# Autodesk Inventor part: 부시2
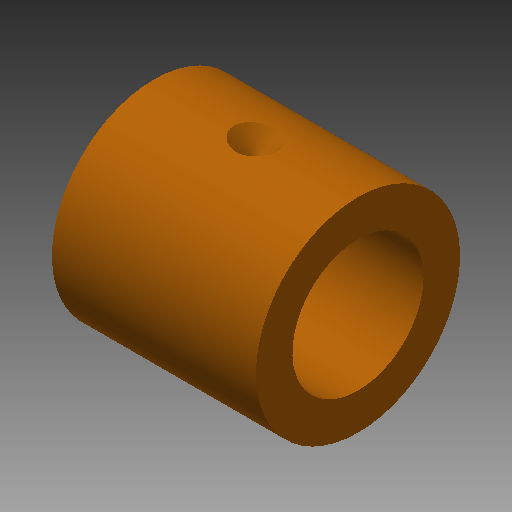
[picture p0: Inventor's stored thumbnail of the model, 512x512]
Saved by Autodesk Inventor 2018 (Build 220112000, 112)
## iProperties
Created: 2020-03
Part Number: 부시2
Material: 스테인리스강
Document SubType Name: Modeling
Designer: mduedu
Density: 8.08 g/cm^3
Appearance: 주황색
Mass: 10.1904 g
Surface Area: 11.9486 cm^2
Volume: 1.26119 cm^3
Author: mduedu
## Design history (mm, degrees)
sketch "스케치2"
  geometry: C1 r 7 at (0, 0); C2 r 4.5 at (0, 0); 1 further point
  constraints: 2 centre point, 2 coincident
  dimensions: "d15" = 14 diameter of C1; "d16" = 9 diameter of C2
extrude "돌출1" new body sketch "스케치2" distance "d17" = 14; taper "d18" = 0 deg
sketch "스케치3"
  geometry: L1 (0, -7)-(-14, -7) reference; L2 (-14, -7)-(-14, -4.5) reference; L3 (-14, -4.5)-(0, -4.5) reference; L4 (0, -4.5)-(0, -7) reference; L5 (-14, 7)-(0, 7) reference; L6 (0, 7)-(0, 4.5) reference; L7 (0, 4.5)-(-14, 4.5) reference; L8 (-14, 4.5)-(-14, 7) reference; L9 (-7, 7)-(-7, 5.5); L10 (-7, 5.5)-(-5.5, 7); L11 (-5.5, 7)-(-7, 7); 1 further point
  constraints: 6 end point, 1 collinear, 1 midpoint, 1 parallel, 1 point on line
  dimensions: "d19" = 3 diameter of L10.end L9; "d21" = 7 distance between parallel lines of L6 L9; "d22" = 45 deg angle of L10 L9
revolve "회전2" sketch "스케치3" stored, may be unused: angle "d23" = 90 deg
node "작업점1"
node "솔리드2"
node "절단 모서리 투영1"
